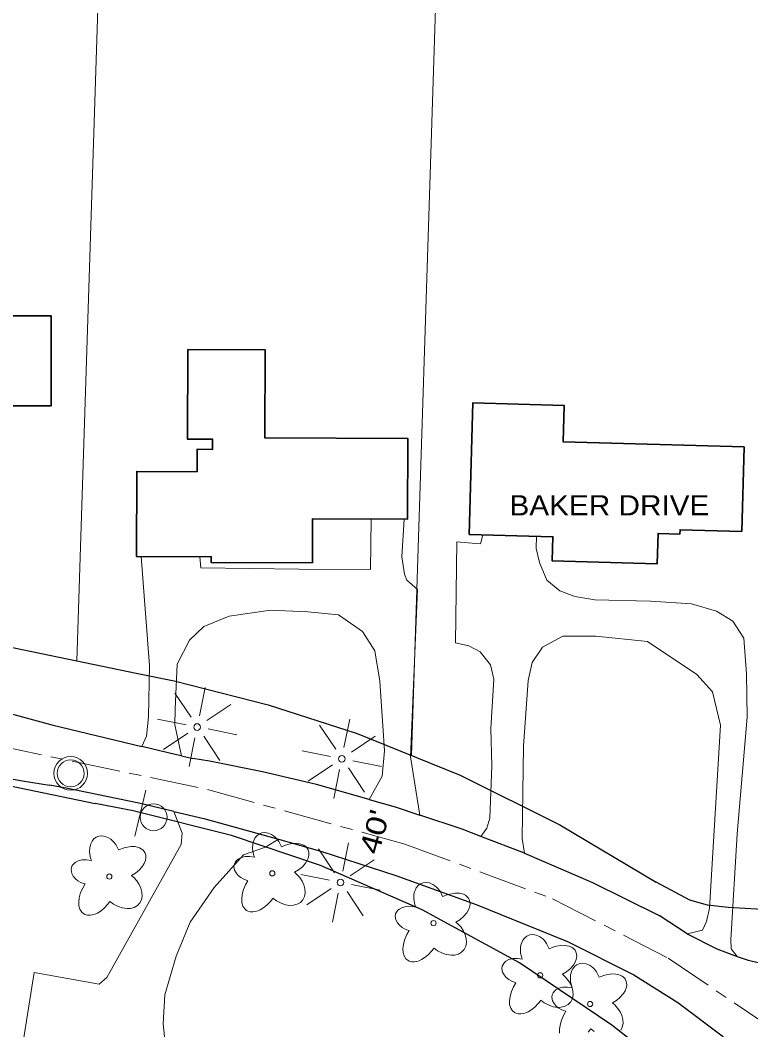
# Model space of a CAD drawing. Extents: x -861682 to -858969, y -1797841 to -1795153.
# Drawn here: x -859504.4 to -859287.5, y -1795757.2 to -1795457.4 of the extents above; entities that cross this region are included whole.
import ezdxf

# ---------------------------------------------------------------- set-up
doc = ezdxf.new("R2010")
doc.units = 0
doc.header["$LTSCALE"] = 2.4
doc.linetypes.add('LONG_DASH_SHORT_DASH', pattern=[9.9, 6, -1.2, 1.5, -1.2])
for name, color, linetype, lineweight in [('10', 7, 'Continuous', 25), ('11', 7, 'Continuous', 13), ('12', 7, 'Continuous', 35), ('17', 7, 'Continuous', 13), ('21', 7, 'Continuous', 13), ('30', 7, 'Continuous', 13), ('32', 7, 'LONG_DASH_SHORT_DASH', 13), ('36', 7, 'Continuous', 13), ('42', 7, 'Continuous', 25), ('46', 7, 'Continuous', 13)]:
    doc.layers.add(name, color=color, linetype=linetype, lineweight=lineweight)
doc.layers.add('43', color=7, linetype='Continuous')

msp = doc.modelspace()

# ---------------------------------------------------------------- linework, layer by layer
at = {"layer": '10'}
for p, q in [((-859456.558, -1795675.86), (-859453.149, -1795676.614)), ((-859354.734, -1795704.729), (-859367.654, -1795699.778)), ((-859306.464, -1795728.685), (-859314.747, -1795723.241))]:
    msp.add_line(p, q, dxfattribs=at)
for points in [[(-859609.372, -1795654.276), (-859590.772, -1795661.166), (-859570.868, -1795667.661), (-859551.784, -1795673.068), (-859534.658, -1795677.257), (-859518.482, -1795680.654), (-859504.38, -1795683.179), (-859500.635, -1795683.782), (-859495.693, -1795684.535)], [(-859518.398, -1795660.345), (-859494.988, -1795666.647), (-859468.323, -1795673.059)], [(-859456.558, -1795675.86), (-859458.032, -1795675.535), (-859468.323, -1795673.059)], [(-859400.836, -1795688.815), (-859416.443, -1795684.415), (-859432.531, -1795680.62), (-859448.226, -1795677.484), (-859453.149, -1795676.614)], [(-859458.783, -1795692.353), (-859469.202, -1795689.887), (-859490.777, -1795685.449), (-859495.693, -1795684.535)], [(-859400.836, -1795688.815), (-859393.112, -1795690.993), (-859385.797, -1795693.439)], [(-859458.783, -1795692.353), (-859449.9, -1795694.456), (-859427.7, -1795700.65)], [(-859367.654, -1795699.778), (-859373.256, -1795697.633), (-859385.797, -1795693.439)], [(-859427.7, -1795700.65), (-859414.876, -1795704.229), (-859392.868, -1795711.379), (-859369.045, -1795720.031), (-859346.563, -1795729.099)], [(-859354.734, -1795704.729), (-859334.525, -1795713.518), (-859314.747, -1795723.241)], [(-859346.563, -1795729.099), (-859341.946, -1795731.02), (-859322.267, -1795740.882), (-859309.217, -1795749.103), (-859296.016, -1795759.043), (-859285.303, -1795768.548)], [(-859306.464, -1795728.685), (-859297.606, -1795733.133), (-859291.594, -1795735.461)], [(-859291.594, -1795735.461), (-859288.291, -1795736.524), (-859277.069, -1795739.077), (-859272.109, -1795739.71)]]:
    msp.add_lwpolyline(points, dxfattribs=at)
at = {"layer": '11'}
for points in [[(-859400.194, -1795605.533), (-859400.417, -1795620.504), (-859421.706, -1795620.423), (-859450.848, -1795620.038), (-859451.108, -1795616.731)], [(-859390.436, -1795605.572), (-859391.139, -1795616.742), (-859390.307, -1795621.919), (-859389.599, -1795623.681), (-859386.49, -1795626.493), (-859388.531, -1795676.202), (-859385.797, -1795693.439)], [(-859367.058, -1795610.221), (-859367.76, -1795612.848), (-859369.165, -1795612.838), (-859374.757, -1795612.311), (-859375.19, -1795642.294), (-859371.237, -1795643.22), (-859367.854, -1795644.923), (-859364.842, -1795648.818), (-859363.854, -1795653.09), (-859364.681, -1795667.696), (-859364.399, -1795678.85), (-859364.995, -1795694.347), (-859365.868, -1795697.355), (-859367.654, -1795699.778)], [(-859351.185, -1795610.662), (-859351.256, -1795614.274), (-859350.299, -1795618.474), (-859348.067, -1795623.731), (-859344.202, -1795626.831), (-859339.763, -1795628.488), (-859333.883, -1795629.523), (-859317.284, -1795629.901), (-859305.104, -1795630.731), (-859297.672, -1795632.908), (-859292.847, -1795635.817), (-859289.623, -1795640.919), (-859288.853, -1795651.539), (-859288.595, -1795664.343), (-859291.614, -1795699.064), (-859293.467, -1795730.548), (-859293.338, -1795733.225), (-859291.594, -1795735.461)], [(-859468.483, -1795616.659), (-859466.053, -1795649.044), (-859466.351, -1795664.242), (-859466.889, -1795670.009), (-859468.323, -1795673.059)], [(-859456.558, -1795675.86), (-859458.549, -1795666.686), (-859458.423, -1795661.985), (-859457.806, -1795648.597), (-859454.171, -1795641.494), (-859449.866, -1795637.451), (-859442.383, -1795634.361), (-859430.09, -1795632.598), (-859419.014, -1795633.084), (-859409.896, -1795634.022), (-859402.828, -1795638.885), (-859399.148, -1795644.645), (-859397.66, -1795653.724), (-859396.3, -1795674.392), (-859397.006, -1795681.906), (-859400.836, -1795688.815)], [(-859306.464, -1795728.685), (-859301.878, -1795727.682), (-859300.642, -1795725.082), (-859299.818, -1795721.087), (-859296.533, -1795666.775), (-859298.924, -1795656.872), (-859303.547, -1795651.655), (-859318.247, -1795641.934), (-859333.513, -1795640.366), (-859343.348, -1795640.302), (-859349.399, -1795643.543), (-859352.471, -1795648.148), (-859353.617, -1795653.494), (-859355.004, -1795673.022), (-859355.43, -1795700.405), (-859354.734, -1795704.729)], [(-859504.257, -1795765.187), (-859500.241, -1795740.223), (-859481.007, -1795743.701), (-859478.748, -1795741.651), (-859456.627, -1795702.214), (-859456.367, -1795698.855), (-859458.783, -1795692.353)], [(-859460.559, -1795766.543), (-859461.108, -1795763.978), (-859462.029, -1795755.422), (-859461.475, -1795746.88), (-859458.155, -1795735.403), (-859453.997, -1795725.272), (-859446.843, -1795714.96), (-859438.175, -1795705.226), (-859431.584, -1795702.999), (-859427.7, -1795700.65)]]:
    msp.add_lwpolyline(points, dxfattribs=at)
at = {"layer": '12'}
for points in [[(-859518.141, -1795529.67), (-859545.198, -1795529.684), (-859545.185, -1795554.233), (-859535.947, -1795554.228), (-859535.939, -1795569.024), (-859539.203, -1795569.026), (-859539.19, -1795591.031), (-859518.171, -1795591.019), (-859518.182, -1795571.95), (-859495.235, -1795571.937), (-859495.25, -1795545.14), (-859518.132, -1795545.153)], [(-859417.692, -1795618.562), (-859447.692, -1795618.445), (-859447.685, -1795616.745), (-859469.938, -1795616.653), (-859469.834, -1795591.391), (-859451.927, -1795591.465), (-859451.9, -1795584.812), (-859447.329, -1795584.831), (-859447.317, -1795581.849), (-859454.754, -1795581.819), (-859454.647, -1795555.203), (-859431.678, -1795555.295), (-859431.783, -1795581.414), (-859389.379, -1795581.584), (-859389.475, -1795605.576), (-859417.64, -1795605.463)], [(-859289.525, -1795584.075), (-859343.271, -1795582.578), (-859342.97, -1795571.768), (-859370.024, -1795571.015), (-859371.112, -1795610.108), (-859346.27, -1795610.799), (-859346.469, -1795617.956), (-859315.313, -1795618.822), (-859315.062, -1795609.802), (-859308.561, -1795609.983), (-859308.525, -1795608.706), (-859290.234, -1795609.222)]]:
    msp.add_lwpolyline(points, close=True, dxfattribs=at)
at = {"layer": '17'}
for p, q in [((-859453.682, -1795664.413), (-859458.472, -1795657.285)), ((-859451.222, -1795663.953), (-859449.496, -1795655.553)), ((-859449.022, -1795665.353), (-859441.926, -1795660.613)), ((-859455.182, -1795666.613), (-859463.644, -1795664.939)), ((-859408.3, -1795673.394), (-859406.574, -1795664.994)), ((-859454.642, -1795669.113), (-859461.868, -1795673.969)), ((-859448.582, -1795667.873), (-859440.102, -1795669.597)), ((-859410.76, -1795673.854), (-859415.55, -1795666.726)), ((-859454.262, -1795679.073), (-859452.582, -1795670.473)), ((-859449.922, -1795670.013), (-859445.122, -1795677.227)), ((-859406.1, -1795674.794), (-859399.004, -1795670.054)), ((-859412.26, -1795676.054), (-859420.722, -1795674.38)), ((-859411.72, -1795678.554), (-859418.946, -1795683.41)), ((-859405.66, -1795677.314), (-859397.18, -1795679.038)), ((-859411.34, -1795688.514), (-859409.66, -1795679.914)), ((-859407, -1795679.454), (-859402.2, -1795686.668)), ((-859408.667, -1795710.12), (-859406.941, -1795701.72)), ((-859411.127, -1795710.58), (-859415.917, -1795703.452)), ((-859406.467, -1795711.52), (-859399.371, -1795706.78)), ((-859412.627, -1795712.78), (-859421.089, -1795711.106)), ((-859406.027, -1795714.04), (-859397.547, -1795715.764)), ((-859412.087, -1795715.28), (-859419.313, -1795720.136)), ((-859411.707, -1795725.24), (-859410.027, -1795716.64)), ((-859407.367, -1795716.18), (-859402.567, -1795723.394))]:
    msp.add_line(p, q, dxfattribs=at)
for points in [[(-859429.406, -1795718.176), (-859428.364, -1795718.944), (-859426.958, -1795719.666), (-859425.71, -1795720.072), (-859424.338, -1795720.268), (-859423.32, -1795720.218), (-859422.176, -1795719.928), (-859421.244, -1795719.376), (-859420.504, -1795718.588), (-859420.036, -1795717.63), (-859419.826, -1795716.552), (-859419.93, -1795715.356), (-859420.22, -1795714.184), (-859420.706, -1795713.124), (-859421.428, -1795711.98), (-859422.294, -1795711.06), (-859422.976, -1795710.448), (-859421.794, -1795709.732), (-859420.648, -1795708.784), (-859419.728, -1795707.692), (-859419.206, -1795706.836), (-859418.874, -1795706.022), (-859418.728, -1795705.206), (-859418.768, -1795704.444), (-859418.984, -1795703.764), (-859419.242, -1795703.312), (-859419.662, -1795702.838), (-859420.122, -1795702.484), (-859420.688, -1795702.194), (-859421.924, -1795701.866), (-859423.166, -1795701.832), (-859425.212, -1795702.208), (-859426.872, -1795702.846), (-859427.662, -1795701.268), (-859428.316, -1795700.454), (-859428.728, -1795700.052), (-859429.192, -1795699.652), (-859429.794, -1795699.26), (-859430.798, -1795698.828), (-859431.812, -1795698.658), (-859432.7, -1795698.758), (-859433.5, -1795699.092), (-859434.166, -1795699.578), (-859434.726, -1795700.284), (-859435.076, -1795701.04), (-859435.234, -1795701.478), (-859435.402, -1795702.154), (-859435.454, -1795703.316), (-859435.382, -1795704.214), (-859435.17, -1795705.176), (-859434.886, -1795705.982), (-859436.328, -1795705.75), (-859437.686, -1795705.8), (-859438.844, -1795706.086), (-859439.732, -1795706.584), (-859440.172, -1795706.928), (-859440.606, -1795707.494), (-859440.844, -1795708.028), (-859440.968, -1795708.706), (-859440.766, -1795709.81), (-859440.31, -1795710.622), (-859439.686, -1795711.384), (-859438.908, -1795712), (-859438.21, -1795712.424), (-859437.546, -1795712.712), (-859436.818, -1795712.95), (-859437.502, -1795714.162), (-859438.124, -1795715.53), (-859438.52, -1795717.032), (-859438.654, -1795718.366), (-859438.644, -1795719.456), (-859438.31, -1795720.474), (-859437.788, -1795721.32), (-859437.23, -1795721.756), (-859436.844, -1795722.002), (-859436.11, -1795722.226), (-859435.316, -1795722.238), (-859434.546, -1795722.114), (-859433.886, -1795721.902), (-859433.142, -1795721.58), (-859432.066, -1795720.9), (-859431.104, -1795720.114), (-859430.148, -1795719.096), (-859429.402, -1795718.186)], [(-859477.776, -1795719.137), (-859476.734, -1795719.905), (-859475.328, -1795720.627), (-859474.08, -1795721.033), (-859472.708, -1795721.229), (-859471.69, -1795721.179), (-859470.546, -1795720.889), (-859469.614, -1795720.337), (-859468.874, -1795719.549), (-859468.406, -1795718.591), (-859468.196, -1795717.513), (-859468.3, -1795716.317), (-859468.59, -1795715.145), (-859469.076, -1795714.085), (-859469.798, -1795712.941), (-859470.664, -1795712.021), (-859471.346, -1795711.409), (-859470.164, -1795710.693), (-859469.018, -1795709.745), (-859468.098, -1795708.653), (-859467.576, -1795707.797), (-859467.244, -1795706.983), (-859467.098, -1795706.167), (-859467.138, -1795705.405), (-859467.354, -1795704.725), (-859467.612, -1795704.273), (-859468.032, -1795703.799), (-859468.492, -1795703.445), (-859469.058, -1795703.155), (-859470.294, -1795702.827), (-859471.536, -1795702.793), (-859473.582, -1795703.169), (-859475.242, -1795703.807), (-859476.032, -1795702.229), (-859476.686, -1795701.415), (-859477.098, -1795701.013), (-859477.562, -1795700.613), (-859478.164, -1795700.221), (-859479.168, -1795699.789), (-859480.182, -1795699.619), (-859481.07, -1795699.719), (-859481.87, -1795700.053), (-859482.536, -1795700.539), (-859483.096, -1795701.245), (-859483.446, -1795702.001), (-859483.604, -1795702.439), (-859483.772, -1795703.115), (-859483.824, -1795704.277), (-859483.752, -1795705.175), (-859483.54, -1795706.137), (-859483.256, -1795706.943), (-859484.698, -1795706.711), (-859486.056, -1795706.761), (-859487.214, -1795707.047), (-859488.102, -1795707.545), (-859488.542, -1795707.889), (-859488.976, -1795708.455), (-859489.214, -1795708.989), (-859489.338, -1795709.667), (-859489.136, -1795710.771), (-859488.68, -1795711.583), (-859488.056, -1795712.345), (-859487.278, -1795712.961), (-859486.58, -1795713.385), (-859485.916, -1795713.673), (-859485.188, -1795713.911), (-859485.872, -1795715.123), (-859486.494, -1795716.491), (-859486.89, -1795717.993), (-859487.024, -1795719.327), (-859487.014, -1795720.417), (-859486.68, -1795721.435), (-859486.158, -1795722.281), (-859485.6, -1795722.717), (-859485.214, -1795722.963), (-859484.48, -1795723.187), (-859483.686, -1795723.199), (-859482.916, -1795723.075), (-859482.256, -1795722.863), (-859481.512, -1795722.541), (-859480.436, -1795721.861), (-859479.474, -1795721.075), (-859478.518, -1795720.057), (-859477.772, -1795719.147)], [(-859381.543, -1795732.973), (-859380.501, -1795733.741), (-859379.095, -1795734.463), (-859377.847, -1795734.869), (-859376.475, -1795735.065), (-859375.457, -1795735.015), (-859374.313, -1795734.725), (-859373.381, -1795734.173), (-859372.641, -1795733.385), (-859372.173, -1795732.427), (-859371.963, -1795731.349), (-859372.067, -1795730.153), (-859372.357, -1795728.981), (-859372.843, -1795727.921), (-859373.565, -1795726.777), (-859374.431, -1795725.857), (-859375.113, -1795725.245), (-859373.931, -1795724.529), (-859372.785, -1795723.581), (-859371.865, -1795722.489), (-859371.343, -1795721.633), (-859371.011, -1795720.819), (-859370.865, -1795720.003), (-859370.905, -1795719.241), (-859371.121, -1795718.561), (-859371.379, -1795718.109), (-859371.799, -1795717.635), (-859372.259, -1795717.281), (-859372.825, -1795716.991), (-859374.061, -1795716.663), (-859375.303, -1795716.629), (-859377.349, -1795717.005), (-859379.009, -1795717.643), (-859379.799, -1795716.065), (-859380.453, -1795715.251), (-859380.865, -1795714.849), (-859381.329, -1795714.449), (-859381.931, -1795714.057), (-859382.935, -1795713.625), (-859383.949, -1795713.455), (-859384.837, -1795713.555), (-859385.637, -1795713.889), (-859386.303, -1795714.375), (-859386.863, -1795715.081), (-859387.213, -1795715.837), (-859387.371, -1795716.275), (-859387.539, -1795716.951), (-859387.591, -1795718.113), (-859387.519, -1795719.011), (-859387.307, -1795719.973), (-859387.023, -1795720.779), (-859388.465, -1795720.547), (-859389.823, -1795720.597), (-859390.981, -1795720.883), (-859391.869, -1795721.381), (-859392.309, -1795721.725), (-859392.743, -1795722.291), (-859392.981, -1795722.825), (-859393.105, -1795723.503), (-859392.903, -1795724.607), (-859392.447, -1795725.419), (-859391.823, -1795726.181), (-859391.045, -1795726.797), (-859390.347, -1795727.221), (-859389.683, -1795727.509), (-859388.955, -1795727.747), (-859389.639, -1795728.959), (-859390.261, -1795730.327), (-859390.657, -1795731.829), (-859390.791, -1795733.163), (-859390.781, -1795734.253), (-859390.447, -1795735.271), (-859389.925, -1795736.117), (-859389.367, -1795736.553), (-859388.981, -1795736.799), (-859388.247, -1795737.023), (-859387.453, -1795737.035), (-859386.683, -1795736.911), (-859386.023, -1795736.699), (-859385.279, -1795736.377), (-859384.203, -1795735.697), (-859383.241, -1795734.911), (-859382.285, -1795733.893), (-859381.539, -1795732.983)], [(-859349.883, -1795748.469), (-859348.841, -1795749.237), (-859347.435, -1795749.959), (-859346.187, -1795750.365), (-859344.815, -1795750.561), (-859343.797, -1795750.511), (-859342.653, -1795750.221), (-859341.721, -1795749.669), (-859340.981, -1795748.881), (-859340.513, -1795747.923), (-859340.303, -1795746.845), (-859340.407, -1795745.649), (-859340.697, -1795744.477), (-859341.183, -1795743.417), (-859341.905, -1795742.273), (-859342.771, -1795741.353), (-859343.453, -1795740.741), (-859342.271, -1795740.025), (-859341.125, -1795739.077), (-859340.205, -1795737.985), (-859339.683, -1795737.129), (-859339.351, -1795736.315), (-859339.205, -1795735.499), (-859339.245, -1795734.737), (-859339.461, -1795734.057), (-859339.719, -1795733.605), (-859340.139, -1795733.131), (-859340.599, -1795732.777), (-859341.165, -1795732.487), (-859342.401, -1795732.159), (-859343.643, -1795732.125), (-859345.689, -1795732.501), (-859347.349, -1795733.139), (-859348.139, -1795731.561), (-859348.793, -1795730.747), (-859349.205, -1795730.345), (-859349.669, -1795729.945), (-859350.271, -1795729.553), (-859351.275, -1795729.121), (-859352.289, -1795728.951), (-859353.177, -1795729.051), (-859353.977, -1795729.385), (-859354.643, -1795729.871), (-859355.203, -1795730.577), (-859355.553, -1795731.333), (-859355.711, -1795731.771), (-859355.879, -1795732.447), (-859355.931, -1795733.609), (-859355.859, -1795734.507), (-859355.647, -1795735.469), (-859355.363, -1795736.275), (-859356.805, -1795736.043), (-859358.163, -1795736.093), (-859359.321, -1795736.379), (-859360.209, -1795736.877), (-859360.649, -1795737.221), (-859361.083, -1795737.787), (-859361.321, -1795738.321), (-859361.445, -1795738.999), (-859361.243, -1795740.103), (-859360.787, -1795740.915), (-859360.163, -1795741.677), (-859359.385, -1795742.293), (-859358.687, -1795742.717), (-859358.023, -1795743.005), (-859357.295, -1795743.243), (-859357.979, -1795744.455), (-859358.601, -1795745.823), (-859358.997, -1795747.325), (-859359.131, -1795748.659), (-859359.121, -1795749.749), (-859358.787, -1795750.767), (-859358.265, -1795751.613), (-859357.707, -1795752.049), (-859357.321, -1795752.295), (-859356.587, -1795752.519), (-859355.793, -1795752.531), (-859355.023, -1795752.407), (-859354.363, -1795752.195), (-859353.619, -1795751.873), (-859352.543, -1795751.193), (-859351.581, -1795750.407), (-859350.625, -1795749.389), (-859349.879, -1795748.479)], [(-859326.142, -1795757.381), (-859325.674, -1795756.423), (-859325.464, -1795755.345), (-859325.568, -1795754.149), (-859325.858, -1795752.977), (-859326.344, -1795751.917), (-859327.066, -1795750.773), (-859327.932, -1795749.853), (-859328.614, -1795749.241), (-859327.432, -1795748.525), (-859326.286, -1795747.577), (-859325.366, -1795746.485), (-859324.844, -1795745.629), (-859324.512, -1795744.815), (-859324.366, -1795743.999), (-859324.406, -1795743.237), (-859324.622, -1795742.557), (-859324.88, -1795742.105), (-859325.3, -1795741.631), (-859325.76, -1795741.277), (-859326.326, -1795740.987), (-859327.562, -1795740.659), (-859328.804, -1795740.625), (-859330.85, -1795741.001), (-859332.51, -1795741.639), (-859333.3, -1795740.061), (-859333.954, -1795739.247), (-859334.366, -1795738.845), (-859334.83, -1795738.445), (-859335.432, -1795738.053), (-859336.436, -1795737.621), (-859337.45, -1795737.451), (-859338.338, -1795737.551), (-859339.138, -1795737.885), (-859339.804, -1795738.371), (-859340.364, -1795739.077), (-859340.714, -1795739.833), (-859340.872, -1795740.271), (-859341.04, -1795740.947), (-859341.092, -1795742.109), (-859341.02, -1795743.007), (-859340.808, -1795743.969), (-859340.524, -1795744.775), (-859341.966, -1795744.543), (-859343.324, -1795744.593), (-859344.482, -1795744.879), (-859345.37, -1795745.377), (-859345.81, -1795745.721), (-859346.244, -1795746.287), (-859346.482, -1795746.821), (-859346.606, -1795747.499), (-859346.404, -1795748.603), (-859345.948, -1795749.415), (-859345.324, -1795750.177), (-859344.546, -1795750.793), (-859343.848, -1795751.217), (-859343.184, -1795751.505), (-859342.456, -1795751.743), (-859343.14, -1795752.955), (-859343.762, -1795754.323), (-859344.158, -1795755.825), (-859344.292, -1795757.159), (-859344.282, -1795758.249)], [(-859335.786, -1795757.889), (-859335.04, -1795756.979)], [(-859335.044, -1795756.969), (-859334.002, -1795757.737)]]:
    msp.add_lwpolyline(points, dxfattribs=at)
for centre, radius in [((-859451.882, -1795667.313), 1), ((-859408.96, -1795676.754), 1), ((-859477.956, -1795711.725), 0.773), ((-859429.586, -1795710.764), 0.773), ((-859409.327, -1795713.48), 1), ((-859381.723, -1795725.561), 0.773), ((-859350.063, -1795741.057), 0.773), ((-859335.224, -1795749.557), 0.773)]:
    msp.add_circle(centre, radius, dxfattribs=at)
at = {"layer": '21'}
msp.add_line((-859470.347, -1795699.719), (-859467.107, -1795686.095), dxfattribs=at)
msp.add_circle((-859464.837, -1795694.095), 4, dxfattribs=at)
at = {"layer": '30'}
for p, q in [((-859487.593, -1795647.626), (-859472.982, -1795188.82)), ((-859388.228, -1795675.774), (-859372.741, -1795190.285))]:
    msp.add_line(p, q, dxfattribs=at)
at = {"layer": '32'}
msp.add_lwpolyline([(-859608.727, -1795645.905), (-859547.475, -1795663.972), (-859512.218, -1795672.548), (-859448.852, -1795685.888), (-859390.25, -1795702.087), (-859346.418, -1795718.286), (-859312.114, -1795735.914), (-859284.005, -1795754.971), (-859271.617, -1795770.217), (-859251.13, -1795810.238), (-859242.554, -1795833.584), (-859228.738, -1795871.699), (-859218.732, -1795901.238), (-859209.68, -1795935.065), (-859202.057, -1795970.321), (-859196.34, -1796004.625), (-859192.528, -1796042.264), (-859177.759, -1796158.991), (-859172.04, -1796220.929), (-859156.019, -1796407.84)], dxfattribs=at)
at = {"layer": '36'}
for radius in [5, 4]:
    msp.add_circle((-859489.437, -1795681.075), radius, dxfattribs=at)
at = {"layer": '42'}
msp.add_line((-859271.551, -1795722.255), (-859294.243, -1795720.911), dxfattribs=at)
for points in [[(-859576.508, -1795629.228), (-859487.593, -1795647.626), (-859470.03, -1795651.28)], [(-859470.03, -1795651.28), (-859458.764, -1795653.593), (-859430.836, -1795660.68), (-859404.345, -1795669.27), (-859373.812, -1795681.607), (-859344.23, -1795696.306), (-859315.601, -1795713.427)], [(-859668.412, -1795664.234), (-859560.873, -1795673.642), (-859482.19, -1795690.004)], [(-859243.627, -1795852.034), (-859252.875, -1795835.558), (-859269.338, -1795812.162), (-859285.617, -1795793.451), (-859310.747, -1795770.037), (-859328.757, -1795755.826), (-859356.224, -1795737.37), (-859385.126, -1795721.567), (-859415.296, -1795708.481), (-859441.665, -1795699.566), (-859470.894, -1795692.189), (-859482.19, -1795690.004)], [(-859294.243, -1795720.911), (-859300.426, -1795720.169), (-859305.587, -1795718.731), (-859315.601, -1795713.427)]]:
    msp.add_lwpolyline(points, dxfattribs=at)

# ---------------------------------------------------------------- texts
at = {"layer": '43', "width": 1.25}
msp.add_text("40'", height=6, rotation=74.634, dxfattribs=at).set_placement((-859398.049, -1795705.515))
at = {"layer": '46', "width": 1.1}
msp.add_text('BAKER DRIVE', height=6, dxfattribs=at).set_placement((-859359.181, -1795604.451))

doc.saveas('drawing.dxf')
